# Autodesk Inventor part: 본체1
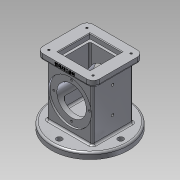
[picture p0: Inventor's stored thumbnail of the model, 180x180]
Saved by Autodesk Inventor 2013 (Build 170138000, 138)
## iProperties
Created: 2018-10
Part Number: 본체1
Material: 알루미늄 6061
Document SubType Name: Modeling
Designer: Administrator
Density: 2.40731 g/cm^3
Mass: 877.844 g
Surface Area: 743.902 cm^2
Volume: 364.657 cm^3
Author: Administrator
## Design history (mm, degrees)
sketch "스케치1"
  geometry: C1 r 62.5 at (0, 0); 1 further point
  constraints: 1 centre point, 1 coincident
  dimensions: "d0" = 125 diameter of C1
extrude "돌출1" new body sketch "스케치1" distance "d1" = 10; taper "d2" = 0 deg
sketch "스케치2"
  geometry: L1 (37, 33)-(-37, 33); L2 (-37, 33)-(-37, -33); L3 (-37, -33)-(37, -33); L4 (37, -33)-(37, 33); L5 (37, 33)-(-37, -33); L6 (-37, 33)-(37, -33); C1 r 62.5 at (0, 0) reference
  constraints: 12 end point, 2 midpoint, 2 parallel, 1 horizontal, 1 perpendicular
  dimensions: "d3" = 74 distance between parallel lines of L4 L2; "d5" = 66 distance between parallel lines of L3 L1
extrude "돌출2" join sketch "스케치2" distance "d6" = 88; taper "d7" = 0 deg
sketch "스케치3"
  geometry: L1 (-25.5, -10)-(99.5, -10) reference; C1 r 35 at (37, 44); 1 further point
  constraints: 1 centre point, 1 vertical alignment
  dimensions: "d8" = 70 diameter of C1; "d9" = 54 distance from line of L1 C1.centre
extrude "돌출3" cut sketch "스케치3" distance "d10" = 3; taper "d11" = 0 deg
sketch "스케치4"
  geometry: L1 (46, -41)-(-46, -41); L2 (-46, -41)-(-46, 41); L3 (-46, 41)-(46, 41); L4 (46, 41)-(46, -41); L5 (46, -41)-(-46, 41); L6 (-46, -41)-(46, 41); 1 further point
  constraints: 12 end point, 2 midpoint, 2 parallel, 1 horizontal, 1 perpendicular
  dimensions: "d12" = 92 distance between parallel lines of L4 L2; "d14" = 82 distance between parallel lines of L1 L3
extrude "돌출4" join sketch "스케치4" distance "d15" = 10; taper "d16" = 0 deg
sketch "스케치5"
  geometry: L1 (26, 26)-(-26, 26); L2 (-26, 26)-(-26, -26); L3 (-26, -26)-(26, -26); L4 (26, -26)-(26, 26); L5 (26, 26)-(-26, -26); L6 (-26, 26)-(26, -26); 1 further point
  constraints: 12 end point, 2 midpoint, 2 parallel, 1 horizontal, 1 perpendicular
  dimensions: "d17" = 52 distance of L3.end L2.end; "d18" = 52 distance of L2.end L1.end
extrude "돌출5" cut sketch "스케치5" distance "d19" = 8; taper "d20" = 0 deg
sketch "스케치6"
  geometry: L1 (22, 22)-(-22, 22); L2 (-22, 22)-(-22, -22); L3 (-22, -22)-(22, -22); L4 (22, -22)-(22, 22); L5 (22, 22)-(-22, -22); L6 (-22, 22)-(22, -22); 1 further point
  constraints: 12 end point, 2 midpoint, 2 parallel, 1 horizontal, 1 perpendicular
  dimensions: "d21" = 44 distance of L3.end L2.end; "d22" = 44 distance of L2.end L1.end
extrude "돌출6" cut sketch "스케치6" distance "d23" = 74; taper "d24" = 0 deg
sketch "스케치7"
  geometry: C1 r 35 at (0, 0) reference; C2 r 24 at (0, 0); 1 further point
  constraints: 1 centre point, 1 coincident
  dimensions: "d25" = 48 diameter of C2
extrude "돌출7" cut sketch "스케치7" stored distance "d26" = 74; taper "d27" = 0 deg
fillet "모깎기1" dims "d28" = 10
sketch "스케치8"
  geometry: C1 r 24 at (0, 0) reference; 2 further points
  constraints: 1 vertical alignment
  dimensions: "d29" = 29 distance of C1.centre point (0, 29)
hole "구멍1" sketch "스케치8" at (0, 29) diameter "d30" = 3.242; stored, may be unused: countersink angle "d34" = 90 deg, drill point angle "d36" = 118 deg; dims "d31" = 4, "d32" = 4, "d33" = 2, "d35" = 6
sketch "스케치9"
  geometry: L1 (10, -29.5)-(10, 95.5) reference; 2 further points
  constraints: 1 horizontal alignment
  dimensions: "d42" = 37 distance from line of L1 point (-27, 33)
hole "구멍2" sketch "스케치9" at (-27, 33) diameter "d43" = 4.134; stored, may be unused: countersink angle "d47" = 90 deg, drill point angle "d49" = 118 deg; dims "d44" = 4, "d45" = 4, "d46" = 2, "d48" = 6
sketch "스케치10"
  geometry: A1 r 10 centre (-36, 31) between (-36, 41) and (-46, 31) reference; A2 r 10 centre (-36, -31) between (-46, -31) and (-36, -41) reference; A3 r 10 centre (36, -31) between (36, -41) and (46, -31) reference; A4 r 10 centre (36, 31) between (46, 31) and (36, 41) reference; 1 further point
hole "구멍3" sketch "스케치10" at (36, 31), (-36, 31), (-36, -31), (36, -31) diameter "d53" = 3.242; stored, may be unused: countersink angle "d57" = 90 deg, drill point angle "d59" = 118 deg; dims "d54" = 4, "d55" = 4, "d56" = 2, "d58" = 6
sketch "스케치11"
  geometry: L1 (0, 0)-(0, 18); L2 (0, 18)-(-24.826, 18); L3 (-62.5, 0)-(62.5, 0) reference; L4 (-24.826, 18)-(-28, 0)
  constraints: 6 end point, 1 perpendicular, 1 point on line, 1 vertical
  dimensions: "d60" = 18 distance between parallel lines of L3 L2; "d61" = 80 deg angle of L3 L4; "d62" = 56 diameter of L4.end L1
revolve "회전1" sketch "스케치11" stored, may be unused: angle "d63" = 90 deg
sketch "스케치12"
  geometry: C1 r 62.5 at (0, 0) reference; C2 r 4.5 at (0, 50)
  constraints: 1 centre point, 1 vertical alignment
  dimensions: "d64" = 9 diameter of C2; "d65" = 50 distance of C1.centre C2.centre
extrude "돌출8" cut sketch "스케치12" stored distance "d66" = 74; taper "d67" = 0 deg
node "작업 평면1"
sketch "스케치13"
  geometry: L1 (-46, 108)-(-46, 98) reference; L2 (-36, 108)-(36, 108) reference; 2 further points
  constraints: 1 other
  dimensions: "d71" = 46 distance from line of L1 point (0, 104); "d72" = 4 distance from line of L2 point (0, 104)
feature "엠보싱1" sketch "스케치13" dims "d73" = 0.5, "d74" = 0
chamfer "모따기1" distance "d75" = 1; stored, may be unused: second distance "d76" = 2, angle "d77" = 45 deg
fillet "모깎기2" dims "d78" = 3
fillet "모깎기3" dims "d79" = 3
fillet "모깎기4" dims "d80" = 3
fillet "모깎기5" dims "d81" = 3
fillet "모깎기6" dims "d82" = 3
fillet "모깎기7" dims "d83" = 3
node "솔리드1"
mirror "대칭1"
pattern_circular "원형 패턴1" dims angle "d38" = 360 deg
mirror "대칭2"
pattern_linear "직사각형 패턴1" dims "d52" = 43
pattern_circular "원형 패턴2" dims angle "d69" = 360 deg
